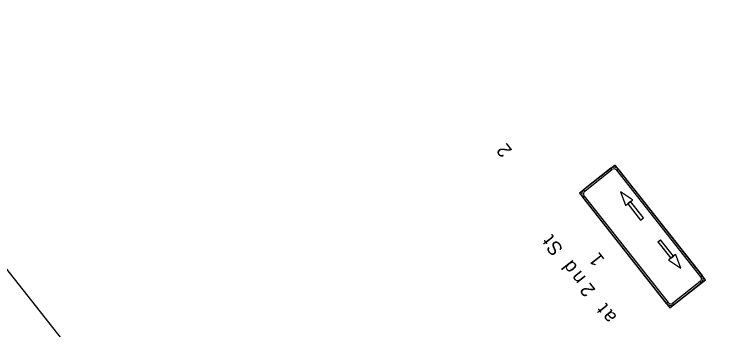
# Model space of a CAD drawing. Extents: x 672239 to 673995, y 1673540 to 1675195.
# Drawn here: x 673278.8 to 673696.1, y 1674449 to 1674630.2 of the extents above; entities that cross this region are included whole.
import ezdxf

# ---------------------------------------------------------------- set-up
doc = ezdxf.new("R2010")
doc.units = 0
doc.layers.add('C-ANNO-SYMB', color=7, linetype='Continuous')
doc.layers.add('C-HELI-DIST', color=7, linetype='Continuous')

msp = doc.modelspace()

# ---------------------------------------------------------------- linework, layer by layer
at = {"layer": 'C-ANNO-SYMB'}
for p, q in [((673624.43, 1674543.61), (673604.01, 1674527.51)), ((673676.43, 1674477.65), (673624.43, 1674543.61)), ((673622.07, 1674541.75), (673606.37, 1674529.37)), ((673606.98, 1674528.59), (673622.69, 1674540.97)), ((673622.07, 1674541.75), (673622.69, 1674540.97)), ((673622.69, 1674540.97), (673622.07, 1674541.75)), ((673622.69, 1674540.97), (673622.07, 1674541.75)), ((673622.69, 1674540.97), (673622.69, 1674540.97)), ((673622.69, 1674540.97), (673622.69, 1674540.97)), ((673625.5, 1674540.64), (673626.28, 1674541.26)), ((673625.5, 1674540.64), (673626.28, 1674541.26)), ((673673.79, 1674479.38), (673625.5, 1674540.64)), ((673626.28, 1674541.26), (673674.57, 1674480)), ((673606.98, 1674528.59), (673606.37, 1674529.37)), ((673606.98, 1674528.59), (673606.37, 1674529.37)), ((673604.01, 1674527.51), (673656.01, 1674461.55)), ((673605.87, 1674525.16), (673606.65, 1674525.78)), ((673605.87, 1674525.16), (673606.65, 1674525.78)), ((673605.87, 1674525.16), (673606.65, 1674525.78)), ((673654.16, 1674463.9), (673605.87, 1674525.16)), ((673606.65, 1674525.78), (673606.65, 1674525.78)), ((673606.65, 1674525.78), (673606.65, 1674525.78)), ((673606.65, 1674525.78), (673654.94, 1674464.52)), ((673627.6, 1674528.28), (673627.6, 1674528.28)), ((673627.6, 1674528.28), (673627.6, 1674528.28)), ((673634.43, 1674523.65), (673627.6, 1674528.28)), ((673627.6, 1674528.28), (673630.51, 1674520.56)), ((673630.67, 1674520.52), (673631.77, 1674521.38)), ((673631.77, 1674521.38), (673633.34, 1674522.62)), ((673633.34, 1674522.62), (673631.77, 1674521.38)), ((673631.77, 1674521.38), (673633.34, 1674522.62)), ((673631.77, 1674521.38), (673639.19, 1674511.96)), ((673633.34, 1674522.62), (673634.44, 1674523.49)), ((673640.77, 1674513.2), (673633.34, 1674522.62)), ((673634.43, 1674523.65), (673634.37, 1674523.57)), ((673634.37, 1674523.57), (673634.43, 1674523.65)), ((673634.37, 1674523.57), (673634.43, 1674523.65)), ((673634.37, 1674523.57), (673634.44, 1674523.49)), ((673634.44, 1674523.49), (673634.37, 1674523.57)), ((673630.6, 1674520.59), (673630.51, 1674520.56)), ((673630.51, 1674520.56), (673630.6, 1674520.59)), ((673630.67, 1674520.52), (673630.6, 1674520.59)), ((673630.6, 1674520.59), (673630.67, 1674520.52)), ((673639.19, 1674511.96), (673640.77, 1674513.2)), ((673640.77, 1674513.2), (673640.77, 1674513.2)), ((673640.77, 1674513.2), (673640.77, 1674513.2)), ((673649.1, 1674499.39), (673650.67, 1674500.63)), ((673658.1, 1674491.21), (673650.67, 1674500.63)), ((673649.1, 1674499.39), (673649.1, 1674499.39)), ((673649.1, 1674499.39), (673649.1, 1674499.39)), ((673649.1, 1674499.39), (673656.53, 1674489.97)), ((673659.2, 1674492.07), (673656.53, 1674489.97)), ((673659.2, 1674492.07), (673658.1, 1674491.21)), ((673659.2, 1674492.07), (673659.26, 1674492)), ((673659.26, 1674492), (673659.2, 1674492.07)), ((673659.26, 1674492), (673659.35, 1674492.03)), ((673659.35, 1674492.03), (673659.26, 1674492)), ((673662.27, 1674484.31), (673659.35, 1674492.03)), ((673656.53, 1674489.97), (673655.43, 1674489.1)), ((673655.49, 1674489.02), (673655.43, 1674489.1)), ((673655.43, 1674489.1), (673655.49, 1674489.02)), ((673655.43, 1674488.94), (673655.49, 1674489.02)), ((673655.49, 1674489.02), (673655.43, 1674488.94)), ((673655.43, 1674488.94), (673662.27, 1674484.31)), ((673658.1, 1674491.21), (673656.53, 1674489.97)), ((673656.53, 1674489.97), (673658.1, 1674491.21)), ((673662.27, 1674484.31), (673662.27, 1674484.31)), ((673662.27, 1674484.31), (673662.27, 1674484.31)), ((673674.57, 1674480), (673673.79, 1674479.38)), ((673674.57, 1674480), (673673.79, 1674479.38)), ((673673.79, 1674479.38), (673673.79, 1674479.38)), ((673673.79, 1674479.38), (673673.79, 1674479.38)), ((673656.01, 1674461.55), (673676.43, 1674477.65)), ((673673.46, 1674476.57), (673657.75, 1674464.19)), ((673658.37, 1674463.41), (673674.08, 1674475.79)), ((673673.46, 1674476.57), (673674.08, 1674475.79)), ((673674.08, 1674475.79), (673673.46, 1674476.57)), ((673674.08, 1674475.79), (673673.46, 1674476.57)), ((673676.43, 1674477.65), (673676.43, 1674477.65)), ((673676.43, 1674477.65), (673676.43, 1674477.65)), ((673654.94, 1674464.52), (673654.16, 1674463.9)), ((673654.94, 1674464.52), (673654.16, 1674463.9)), ((673658.37, 1674463.41), (673657.75, 1674464.19)), ((673658.37, 1674463.41), (673657.75, 1674464.19)), ((673657.75, 1674464.19), (673657.75, 1674464.19)), ((673657.75, 1674464.19), (673657.75, 1674464.19))]:
    msp.add_line(p, q, dxfattribs=at)
for centre, radius, start, end in [((673623.93, 1674539.4), 3, 38.2506, 128.2508), ((673623.93, 1674539.4), 2, 38.2506, 128.2508), ((673608.22, 1674527.02), 3, 128.2505, 218.2508), ((673608.22, 1674527.02), 2, 128.2505, 218.2508), ((673634.37, 1674523.57), 0.1, 308.2504, 55.3534), ((673630.6, 1674520.59), 0.1, 201.148, 308.2504), ((673659.26, 1674492), 0.1, 21.1478, 128.2508), ((673655.49, 1674489.02), 0.1, 128.2506, 235.3535), ((673672.22, 1674478.14), 2, 308.2504, 38.2506), ((673672.22, 1674478.14), 3, 308.2504, 38.2506), ((673656.51, 1674465.76), 3, 218.2508, 308.2504), ((673656.51, 1674465.76), 2, 218.2508, 308.2504)]:
    msp.add_arc(centre, radius, start, end, dxfattribs=at)
at = {"layer": 'C-HELI-DIST'}
msp.add_lwpolyline([(673177.78, 1673539.85), (672546.3, 1674340.87), (673064.6, 1674749.47), (673696.09, 1673948.45)], close=True, dxfattribs=at)

# ---------------------------------------------------------------- texts
at = {"layer": 'C-ANNO-SYMB'}
for s, p in [('2', (673565.56, 1674552.12)), ('t', (673589.96, 1674501.72)), ('S', (673594.97, 1674495.38)), ('1', (673618.77, 1674489.34)), ('d', (673603.19, 1674484.95)), ('n', (673607.99, 1674478.85)), ('2', (673613.54, 1674471.82)), ('t', (673621.07, 1674462.27)), ('a', (673625.77, 1674456.3))]:
    msp.add_text(s, height=8, rotation=128.2505, dxfattribs=at).set_placement(p)

doc.saveas('drawing.dxf')
